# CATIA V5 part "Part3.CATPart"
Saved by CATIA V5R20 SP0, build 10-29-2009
Part number: Part3
Bounding box of the stored display mesh (mm): x 10 to 40, y 130 to 180, z 40 to 70
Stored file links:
  C:\Users\Ehsan Fathi\Desktop\Part3.CATPart
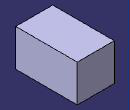
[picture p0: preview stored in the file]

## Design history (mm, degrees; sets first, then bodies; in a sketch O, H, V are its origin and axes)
Body1 (main body)
  DatumSurface1
  Sketch1 on face of DatumSurface1, origin (10, 0, 0), H (0, 1, 0), V (0, 0, 1)
    line L1 (130, 40) -> (180, 40)
    line L2 (180, 40) -> (180, 70)
    line L3 (180, 70) -> (130, 70)
    line L4 (130, 70) -> (130, 40)
    horizontal: L1 H, L3 H
    vertical: L2 V, L4 V
  Pad1: profile Sketch1, direction (1, 0, 0), length 30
